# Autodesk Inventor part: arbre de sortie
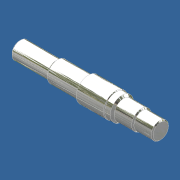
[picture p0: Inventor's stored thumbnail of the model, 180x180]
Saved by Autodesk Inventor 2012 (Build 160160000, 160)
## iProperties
Created: 2011-07
Part Number: arbre de sortie
Document SubType Name: Modeling
Designer: Laur
Density: 7.85 g/cm^3
Material: Acier allié
Mass: 2.98245 g
Surface Area: 3.97681 cm^2
Volume: 0.37993 cm^3
Author: Laur
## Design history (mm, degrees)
sketch "Esquisse1"
  geometry: L1 (0, 0)-(29, 0); L2 (0, 0)-(0, 1.57); L3 (0, 1.57)-(0.2, 1.77); L4 (0.2, 1.77)-(4.5, 1.77); L5 (4.5, 1.77)-(4.5, 1.77); L6 (4.5, 1.77)-(7, 1.77); L7 (7, 1.77)-(7, 1.77); L8 (7, 1.77)-(7.5, 1.77); L9 (11.53, 2.1)-(14.03, 2.1); L10 (14.03, 2.1)-(14.03, 2.5); L11 (14.03, 2.5)-(19.63, 2.5); L12 (19.63, 2.5)-(19.75, 2.38); L13 (19.75, 2.38)-(20.73, 2.38); L14 (20.73, 2.38)-(21.01, 2.1); L15 (21.01, 2.1)-(22.98, 2.1); L16 (22.98, 2.1)-(23.08, 2); L17 (23.08, 2)-(24.48, 2); L18 (24.48, 2)-(24.71, 1.77); L19 (24.71, 1.77)-(28.8, 1.77); L20 (28.8, 1.77)-(29, 1.57); L21 (29, 1.57)-(29, 0); L22 (7.73, 2)-(7.5, 1.77); L23 (7.73, 2)-(11.43, 2); L24 (11.43, 2)-(11.53, 2.1)
  constraints: 49 end point, 11 parallel, 7 perpendicular, 2 collinear, 1 horizontal
  dimensions: "d0" = 45 deg angle of L2 L3; "d1" = 45 deg angle of L15 L14 (= d0); "d2" = 45 deg angle of L17 L16 (= d0); "d3" = 0.2 distance from line of L2 L3.end; "d4" = 3.54 diameter of L4 L1; "d5" = 7 distance between parallel lines of L7 L2; "d6" = 3.54 diameter of L6 L1 (= d4); "d7" = 4.5 distance from line of L4.end L2; "d8" = 2.5 distance of L7.end L5.end; "d10" = 4.2 diameter of L9 L1; "d13" = 5.6 distance from line of L11.end L10; "d14" = 5 diameter of L11 L1; "d15" = 4.76 diameter of L13 L1; "d16" = 4.2 diameter of L15 L1; "d17" = 4 diameter of L17 L1; "d18" = 3.54 diameter of L19 L1 (= d4); "d19" = 1.1 horizontal distance of L13.end L11.end; "d21" = 2.25 horizontal distance of L15.end L13.end; "d22" = 1.5 horizontal distance of L17.end L15.end; "d23" = 0.2 horizontal distance of L20.end L19.end; "d24" = 29 distance between parallel lines of L21 L2; "d26" = 0.5 distance of L6.end L8.end; "d27" = 6.3 distance from line of L22.start L10; "d29" = 4 diameter of L23 L1; "d30" = 3.8 horizontal distance of L22.start L9.start
revolve "toutes les formes de l'arbre" sketch "Esquisse1" stored, may be unused: angle "d28" = 90 deg
node "Solide1"
node "Corps solides"
node "Corps surfaciques"
